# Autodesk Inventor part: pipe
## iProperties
Shininess: 64.0
Length Units: 11269
Angle Units: 11279
Time Units: 11290
Mass Units: 11286
Length Display Precision: 3
Angle Display Precision: 2
Compacted: True
Part Number: pipe
Document SubType Name: Modeling
Created: 2002-11
Designer: Elise Moss
Density: 0.0
Volumn: 0.0
Area: 0.0
PropertySet Name: Model Information
Control State: 0
Master: False
Checked Out: False
Author: Elise Moss
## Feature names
1. Extrusion1
2. Shell1
